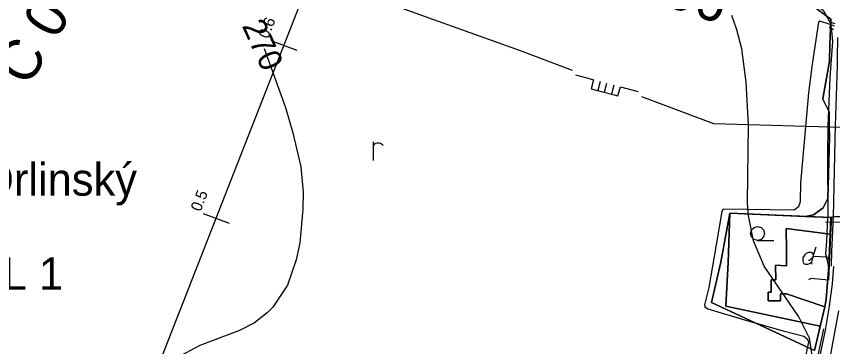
# Model space of a CAD drawing. Extents: x -645676 to -642474, y -1077513 to -1072613.
# Drawn here: x -645010.7 to -644570.9, y -1075082.2 to -1074904.3 of the extents above; entities that cross this region are included whole.
import ezdxf

# ---------------------------------------------------------------- set-up
doc = ezdxf.new("R2010")
doc.units = 0
for name, color, linetype in [('katastr_ln___zem____popis', 7, 'Continuous'), ('KULTURY_STAV', 7, 'Continuous'), ('KULTURY_ZNACKY', 7, 'Continuous'), ('NERESENE_POZEMKY', 7, 'Continuous'), ('Obvod_KP_', 7, 'Continuous'), ('OBVOD_PU', 7, 'Continuous'), ('P__kop___st_vaj_c_', 7, 'Continuous'), ('PC_NAVRH', 7, 'Continuous'), ('PC_POPIS_NAVRH', 7, 'Continuous'), ('PC_STAN_NAVRH', 7, 'Continuous'), ('PLYNOVOD', 7, 'Continuous'), ('Popis___Vodn__n_dr____navr_ena', 7, 'Continuous'), ('SDELOVACI', 7, 'Continuous'), ('Silnice_II__t__dy_a_III__t__dy', 7, 'Continuous'), ('VODOVOD', 7, 'Continuous'), ('VRSTEVNICE', 7, 'Continuous'), ('Vrstevnice_zd_razn_n____popis', 7, 'Continuous')]:
    doc.layers.add(name, color=color, linetype=linetype)

# ---------------------------------------------------------------- blocks, each defined once
blk = doc.blocks.new('$944')
blk.add_line((0, 1.5), (0, -1.5))
blk = doc.blocks.new('3$0400')
blk.add_lwpolyline([(0, 0), (-0.38, 0.1), (-0.65, 0.38), (-0.75, 0.75), (-0.65, 1.12), (-0.38, 1.4), (0, 1.5), (0.38, 1.4), (0.65, 1.12), (0.75, 0.75), (0.65, 0.38), (0.38, 0.1), (0, 0), (1.75, 0)])
blk = doc.blocks.new('$431')
blk.add_line((0.63, 0.99), (0.9, 1.89))
blk.add_lwpolyline([(0.45, 0), (0.45, 0.27), (0.63, 0.99), (0.54, 1.17), (0.36, 1.26), (0.09, 1.26), (-0.18, 1.17), (-0.36, 0.99), (-0.54, 0.72), (-0.54, 0.36), (-0.45, 0.09), (-0.27, 0), (0, 0), (0.18, 0.09), (0.45, 0.27)])
blk = doc.blocks.new('$479')
for points in [[(0, 0), (0, 1.27), (0, 2)], [(0, 1.6), (0.1, 1.73), (0.23, 1.84), (0.37, 1.89), (0.6, 1.9), (0.77, 1.87), (0.87, 1.8), (0.96, 1.7), (1, 1.6)]]:
    blk.add_lwpolyline(points)
blk = doc.blocks.new('6$3520')
for p, q in [((-0.76, 0), (-0.76, -1)), ((0, -1), (0, 0)), ((0.76, 0), (0.76, -1))]:
    blk.add_line(p, q)
blk.add_lwpolyline([(-3.5, 0), (-2.23, 0), (-1.48, 0), (-1.48, -1), (-0.21, -1), (1.06, -1), (1.5, -1), (1.5, 0), (2.77, 0), (3.5, 0)])

msp = doc.modelspace()

# ---------------------------------------------------------------- linework, layer by layer
at = {"layer": 'KULTURY_STAV'}
for points in [[(-644582.1, -1074898.35), (-644571.94, -1074905.75), (-644572.1, -1074911.08), (-644572.36, -1074919.52), (-644572.63, -1074928.48), (-644576.21, -1074948.7), (-644576.24, -1074948.88), (-644572.74, -1074955.72), (-644572.73, -1074964.29), (-644572.59, -1074969.25), (-644573.42, -1075002.34), (-644576.06, -1075007.42), (-644581.22, -1075011.3), (-644585.55, -1075012.13), (-644626.35, -1075010.4), (-644627.18, -1075036.92), (-644628.47, -1075060.38), (-644577.57, -1075071.27), (-644580.71, -1075084.33)], [(-644580.71, -1075084.33), (-644577.57, -1075071.27), (-644575.15, -1075060.82), (-644574.31, -1075056.6), (-644572.97, -1075038.79), (-644572.25, -1075021.71), (-644571.87, -1075012.71), (-644585.55, -1075012.13), (-644581.22, -1075011.3), (-644576.06, -1075007.42), (-644573.42, -1075002.34), (-644572.59, -1074969.25), (-644572.73, -1074964.29), (-644572.74, -1074955.72), (-644576.24, -1074948.88), (-644576.21, -1074948.7), (-644572.63, -1074928.48), (-644572.36, -1074919.52), (-644572.1, -1074911.08), (-644571.94, -1074905.75), (-644582.1, -1074898.35)], [(-644626.35, -1075010.4), (-644585.55, -1075012.13), (-644571.87, -1075012.71), (-644572.25, -1075021.71), (-644595.98, -1075018.67), (-644595.73, -1075030.41), (-644595.72, -1075038.71), (-644598.87, -1075038.53), (-644601.6, -1075038.38), (-644601.52, -1075046.29), (-644604, -1075046.31), (-644604.02, -1075052.9), (-644605.68, -1075052.91), (-644605.65, -1075057.51), (-644598.95, -1075057.47), (-644598.97, -1075053.77), (-644595.77, -1075053.75), (-644575.15, -1075060.82), (-644577.57, -1075071.27), (-644628.47, -1075060.38), (-644627.18, -1075036.92), (-644626.35, -1075010.4)], [(-644595.98, -1075018.67), (-644572.25, -1075021.71), (-644572.97, -1075038.79), (-644574.31, -1075056.6), (-644575.15, -1075060.82), (-644595.77, -1075053.75), (-644598.97, -1075053.77), (-644598.95, -1075057.47), (-644605.65, -1075057.51), (-644605.68, -1075052.91), (-644604.02, -1075052.9), (-644604, -1075046.31), (-644601.52, -1075046.29), (-644601.6, -1075038.38), (-644598.87, -1075038.53), (-644595.72, -1075038.71), (-644595.73, -1075030.41), (-644595.98, -1075018.67)]]:
    msp.add_lwpolyline(points, dxfattribs=at)
at = {"layer": 'NERESENE_POZEMKY'}
msp.add_lwpolyline([(-644626.35, -1075010.4), (-644585.55, -1075012.13), (-644571.87, -1075012.71), (-644572.25, -1075021.71), (-644572.97, -1075038.79), (-644574.31, -1075056.6), (-644575.15, -1075060.82), (-644577.57, -1075071.27), (-644580.71, -1075084.33), (-644636.16, -1075058.45), (-644631.17, -1075036.69), (-644626.35, -1075010.4)], dxfattribs=at)
at = {"layer": 'Obvod_KP_'}
msp.add_lwpolyline([(-644626.35, -1075010.4), (-644631.17, -1075036.69), (-644636.16, -1075058.45), (-644580.71, -1075084.33), (-644575.15, -1075060.82), (-644574.31, -1075056.6), (-644572.97, -1075038.79), (-644572.25, -1075021.71), (-644571.87, -1075012.71)], close=True, dxfattribs=at)
at = {"layer": 'OBVOD_PU'}
msp.add_lwpolyline([(-644631.17, -1075036.69), (-644626.35, -1075010.4), (-644571.87, -1075012.71), (-644572.25, -1075021.71), (-644572.97, -1075038.79), (-644574.31, -1075056.6), (-644575.15, -1075060.82), (-644580.71, -1075084.33), (-644636.16, -1075058.45), (-644631.17, -1075036.69)], dxfattribs=at)
at = {"layer": 'P__kop___st_vaj_c_'}
for points in [[(-644568.25, -1074915.76), (-644568.53, -1074926.8), (-644568.53, -1074930.97), (-644569.54, -1074963.28), (-644569.66, -1074970.78), (-644570.35, -1075004.08), (-644570.6, -1075012.03), (-644571.46, -1075030.88), (-644571.62, -1075038.82)], [(-644575.75, -1075072.55), (-644578.46, -1075085.14), (-644583.36, -1075109.48), (-644588.22, -1075134.43), (-644598.09, -1075183.17), (-644603.76, -1075215.2)]]:
    msp.add_lwpolyline(points, dxfattribs=at)
at = {"layer": 'PC_NAVRH'}
msp.add_lwpolyline([(-644606.41, -1075221.19), (-644836.11, -1075174.98), (-644844.56, -1075176.95), (-644881.27, -1075159.75), (-644907.13, -1075151.69), (-644922.26, -1075148.52), (-644947.39, -1075148.27), (-644953.49, -1075145.83), (-644953.49, -1075141.93), (-644894.93, -1074992.28), (-644829.47, -1074825.22)], dxfattribs=at)
at = {"layer": 'PLYNOVOD'}
for p, q in [((-644576.03, -1074900.89), (-644572.07, -1074908.05)), ((-644572.07, -1074908.05), (-644571.44, -1074912.01)), ((-644571.44, -1074912.01), (-644570.94, -1074917.86)), ((-644570.94, -1074917.86), (-644572.45, -1074937.17)), ((-644572.45, -1074937.17), (-644573.52, -1074963.5)), ((-644573.52, -1074963.5), (-644573.65, -1074978.99)), ((-644573.65, -1074978.99), (-644573.46, -1075012.09)), ((-644573.6, -1075012.62), (-644574.27, -1075025.49)), ((-644573.46, -1075012.09), (-644573.6, -1075012.62)), ((-644574.27, -1075025.49), (-644574.69, -1075032.45)), ((-644574.69, -1075032.45), (-644573.99, -1075035.11)), ((-644573.1, -1075035.15), (-644573.99, -1075035.11)), ((-644573.99, -1075035.11), (-644573.65, -1075036.9)), ((-644573.65, -1075036.9), (-644573.36, -1075038.42)), ((-644573.01, -1075035.15), (-644573.1, -1075035.15)), ((-644572.9, -1075035.15), (-644573.01, -1075035.15)), ((-644573.36, -1075038.42), (-644573.24, -1075039.06)), ((-644573.24, -1075039.06), (-644573.09, -1075039.81))]:
    msp.add_line(p, q, dxfattribs=at)
for points in [[(-644560.43, -1074864.47), (-644577.6, -1074864.54), (-644589.25, -1074869.01), (-644589.89, -1074870.39), (-644590.32, -1074871.85), (-644591.02, -1074873.38), (-644596.2, -1074884.08), (-644597.45, -1074887.02), (-644586.85, -1074892.97), (-644576.03, -1074900.89), (-644572.07, -1074908.05), (-644571.44, -1074912.01), (-644570.94, -1074917.86), (-644572.45, -1074937.17), (-644573.52, -1074963.5), (-644573.65, -1074978.99), (-644573.46, -1075012.09), (-644573.6, -1075012.62), (-644574.27, -1075025.49), (-644574.69, -1075032.45), (-644574, -1075035.11), (-644573.65, -1075036.9)], [(-644836.1, -1074887.55), (-644798.01, -1074901.76), (-644739.28, -1074922.66), (-644711.22, -1074933.27)], [(-644569.84, -1074909.57), (-644572.8, -1074908.45), (-644577.7, -1074906.89), (-644578.43, -1074907.45), (-644581.97, -1074930.1), (-644583.95, -1074945.54), (-644585.3, -1074961.89), (-644588.23, -1074994.04), (-644588.34, -1075004.29), (-644589.21, -1075006.95), (-644591.7, -1075008.79), (-644629.87, -1075008.12), (-644630.5, -1075009.38), (-644632.01, -1075017.86), (-644633.58, -1075027.31), (-644637.5, -1075050.38), (-644639.85, -1075059.72), (-644639.48, -1075061.04), (-644638.07, -1075061.86), (-644617.17, -1075068.2), (-644597.61, -1075073.68), (-644586.41, -1075076.62), (-644584.53, -1075077.93), (-644583.83, -1075079.56), (-644588.3, -1075101.28)], [(-644569.52, -1074908.29), (-644571.74, -1074907.54), (-644572.49, -1074910.56), (-644570.34, -1074911.26)], [(-644673.81, -1074947.43), (-644635.1, -1074962.07), (-644585.11, -1074963.45), (-644571.92, -1074963.81), (-644571.81, -1074963.81), (-644560.02, -1074964.14), (-644552.34, -1074965.15), (-644524.12, -1074975.33)]]:
    msp.add_lwpolyline(points, dxfattribs=at)
at = {"layer": 'SDELOVACI'}
for points in [[(-644556.34, -1074906.43), (-644557.28, -1074908.24), (-644557.74, -1074915.1), (-644557.69, -1074920.5), (-644557.85, -1074927.27), (-644557.9, -1074933.2), (-644558.03, -1074937.6), (-644558.08, -1074942.25), (-644558.25, -1074949.58), (-644558.39, -1074952.38), (-644558.81, -1074958.28), (-644559.21, -1074965.78), (-644559.31, -1074968.82), (-644559.18, -1074975.65), (-644559.31, -1074983.19), (-644558.99, -1074989.62), (-644559.44, -1074998.87), (-644559.82, -1075005.92), (-644560.23, -1075012.36), (-644563.33, -1075012.38), (-644569.77, -1075012.35), (-644571.5, -1075012.42)], [(-644556.34, -1074906.43), (-644557.28, -1074908.24), (-644557.74, -1074915.1), (-644557.69, -1074920.5), (-644557.85, -1074927.27), (-644557.9, -1074933.2), (-644558.03, -1074937.6), (-644558.08, -1074942.25), (-644558.25, -1074949.58), (-644558.39, -1074952.38), (-644558.81, -1074958.28), (-644559.21, -1074965.78), (-644559.31, -1074968.82), (-644559.18, -1074975.65), (-644559.31, -1074983.19), (-644558.99, -1074989.62), (-644559.44, -1074998.87), (-644559.82, -1075005.92), (-644560.23, -1075012.36), (-644563.33, -1075012.38), (-644569.77, -1075012.35), (-644571.5, -1075012.42)], [(-644571.5, -1075012.42), (-644572.1, -1075021.86), (-644572.18, -1075025.56), (-644572.43, -1075030.61), (-644572.54, -1075034.15)], [(-644572.54, -1075034.15), (-644574.39, -1075033.97), (-644580.87, -1075033.7), (-644581.8, -1075034.22), (-644582.97, -1075035.54), (-644583.36, -1075035.78), (-644583.9, -1075035.78)], [(-644572.54, -1075034.15), (-644574.39, -1075033.97), (-644580.87, -1075033.7), (-644581.8, -1075034.22), (-644582.97, -1075035.54), (-644583.36, -1075035.78), (-644583.9, -1075035.78)], [(-644572.54, -1075034.15), (-644573.03, -1075046.47), (-644582.47, -1075045.52), (-644583.87, -1075046.26)], [(-644572.54, -1075034.15), (-644573.03, -1075046.47), (-644582.47, -1075045.52), (-644583.87, -1075046.26)]]:
    msp.add_lwpolyline(points, dxfattribs=at)
at = {"layer": 'Silnice_II__t__dy_a_III__t__dy'}
for p, q in [((-644570.94, -1075048.38), (-644570.21, -1075039.04)), ((-644572.63, -1075060.45), (-644570.94, -1075048.38)), ((-644572.63, -1075060.45), (-644570.94, -1075048.38)), ((-644574.76, -1075073.27), (-644572.63, -1075060.45)), ((-644574.76, -1075073.27), (-644572.63, -1075060.45)), ((-644567.71, -1075062.93), (-644572.45, -1075088.32)), ((-644577.5, -1075086.15), (-644574.76, -1075073.27)), ((-644577.5, -1075086.15), (-644574.76, -1075073.27))]:
    msp.add_line(p, q, dxfattribs=at)
at = {"layer": 'VODOVOD'}
msp.add_line((-644559.53, -1075015.38), (-644574.66, -1075015.23), dxfattribs=at)
at = {"layer": 'VRSTEVNICE'}
for points in [[(-644581.84, -1075086.99), (-644583.27, -1075077.59), (-644589.1, -1075066.2), (-644607.76, -1075038.86), (-644613.6, -1075025.18), (-644616.16, -1075011.51), (-644616.73, -1075004.67), (-644616.16, -1074962.8), (-644617.45, -1074939.73), (-644619.87, -1074921.78), (-644622.43, -1074911.53), (-644625.14, -1074903.84)], [(-644877.1, -1074921.7), (-644865.69, -1074953.4), (-644861.7, -1074967.08), (-644857.43, -1074985.3), (-644856.14, -1074998.98), (-644856.29, -1075008.09), (-644858, -1075026.32), (-644859.85, -1075035.44), (-644864.69, -1075049.11), (-644872.52, -1075060.93), (-644875.51, -1075064.06), (-644882.35, -1075069.48), (-644890.47, -1075073.61), (-644911.83, -1075081.58), (-644924.65, -1075088.42), (-644931.48, -1075094.4), (-644935.76, -1075101.52), (-644937.18, -1075106.5), (-644937.04, -1075117.47)]]:
    msp.add_lwpolyline(points, dxfattribs=at)

# ---------------------------------------------------------------- block references
at = {"layer": 'KULTURY_ZNACKY', "xscale": 5, "yscale": 5}
for name, p in [('$479', (-644818.28, -1074981.9)), ('3$0400', (-644611.33, -1075024.98)), ('$431', (-644584.33, -1075037.83))]:
    msp.add_blockref(name, p, dxfattribs=at)
at = {"layer": 'PC_STAN_NAVRH'}
for p, xscale, yscale, rotation in [((-644866.6, -1074919.99), 4.999999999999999, 5, 69.79753399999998), ((-644903.08, -1075013.1), 5.000000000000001, 4.999999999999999, 69.826687)]:
    msp.add_blockref('$944', p, dxfattribs=dict(at, xscale=xscale, yscale=yscale, rotation=rotation))
at = {"layer": 'PLYNOVOD', "xscale": 4.999999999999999, "yscale": 5.000000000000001, "rotation": -14.799472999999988}
msp.add_blockref('6$3520', (-644692.51, -1074940.35), dxfattribs=at)

# ---------------------------------------------------------------- texts
at = {"layer": 'katastr_ln___zem____popis'}
msp.add_text('Orlinský', height=17.5, dxfattribs=at).set_placement((-645030.22, -1075000.91))
at = {"layer": 'PC_POPIS_NAVRH'}
for s, rotation, p in [('C 06', 341.082, (-644690.42, -1074888.49)), ('C 07', 59.416, (-645004.23, -1074942.82))]:
    msp.add_text(s, height=22, rotation=rotation, dxfattribs=at).set_placement(p)
at = {"layer": 'PC_STAN_NAVRH'}
for s, rotation, p in [('0.6', 68.583, (-644874.99, -1074916.72)), ('0.5', 68.64, (-644911.46, -1075009.83))]:
    msp.add_text(s, height=6, rotation=rotation, dxfattribs=at).set_placement(p)
at = {"layer": 'Popis___Vodn__n_dr____navr_ena'}
msp.add_text('POL 1', height=17.5, dxfattribs=at).set_placement((-645051.83, -1075051.61))
at = {"layer": 'Vrstevnice_zd_razn_n____popis'}
msp.add_text('270', height=12.5, rotation=294.396, dxfattribs=at).set_placement((-644889.28, -1074909.36))

doc.saveas('drawing.dxf')
